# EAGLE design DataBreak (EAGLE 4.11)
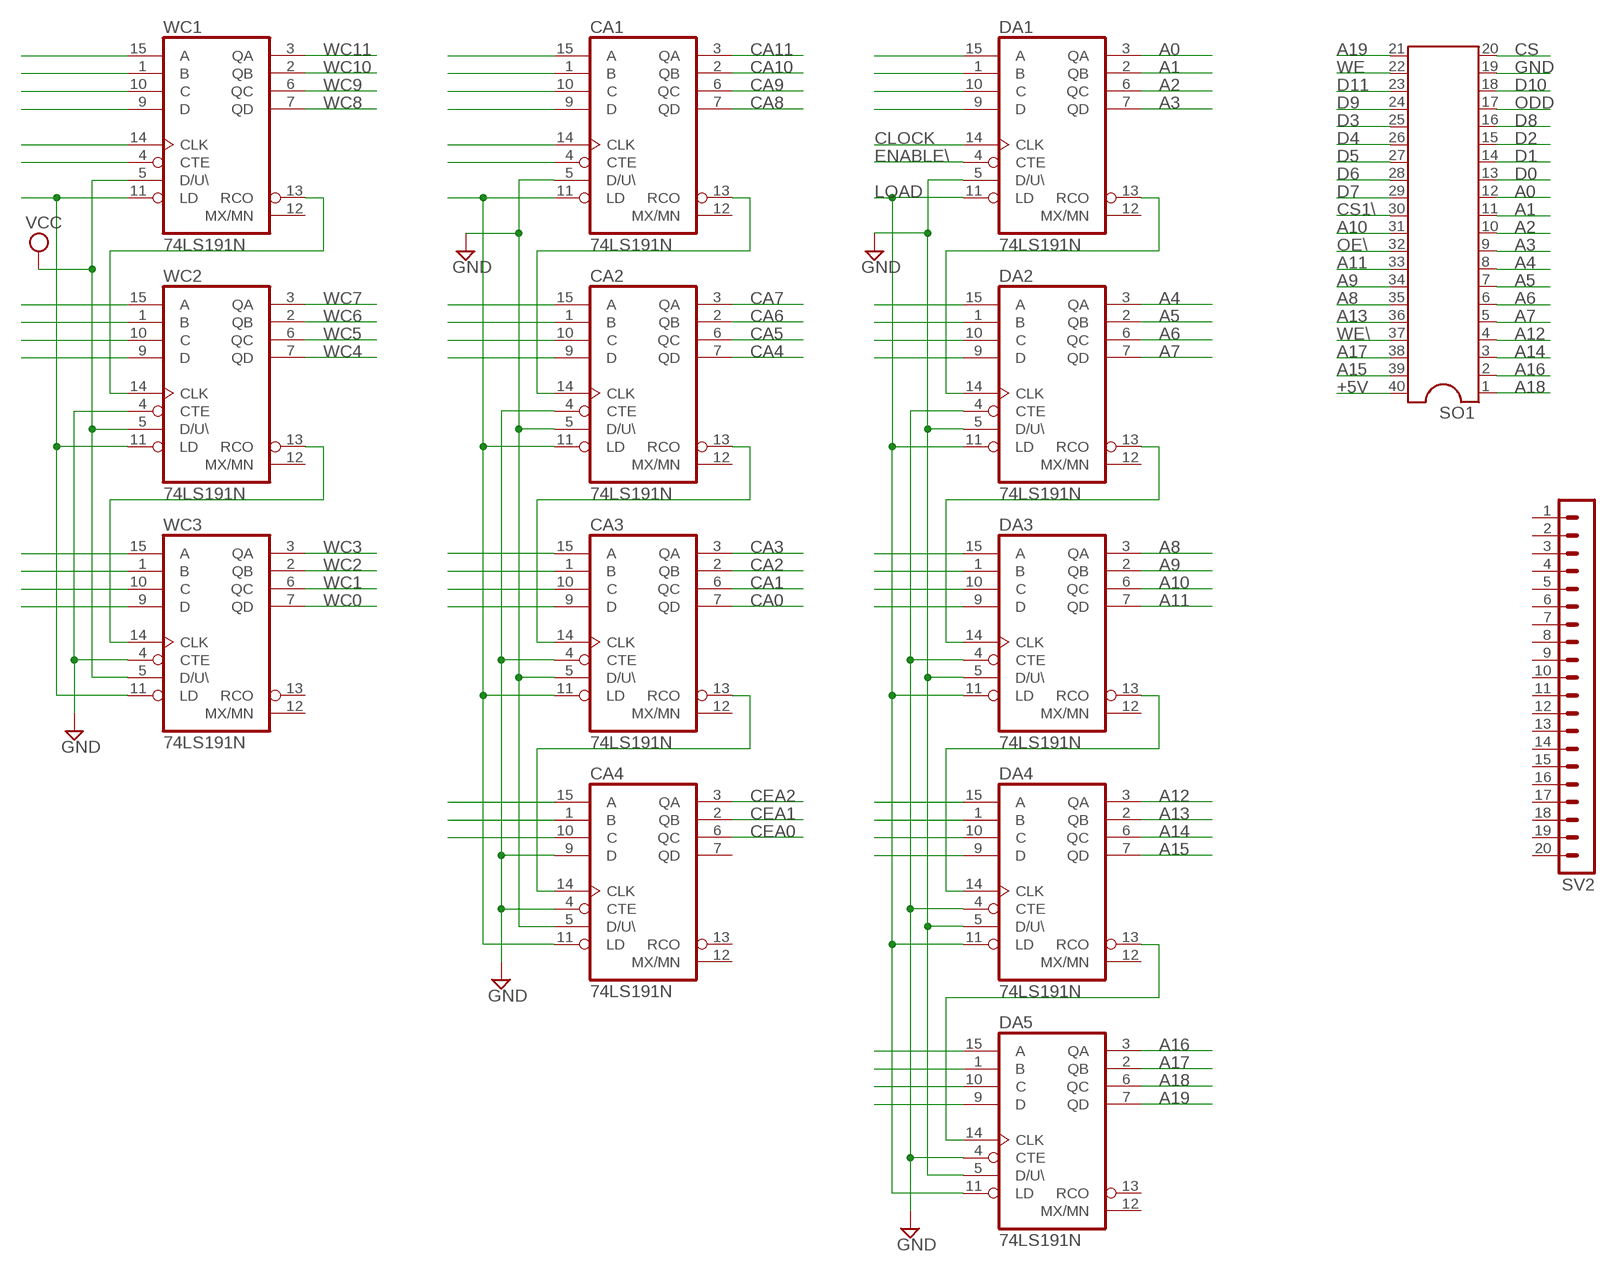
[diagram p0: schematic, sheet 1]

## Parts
CA1  74LS191N  74LS190N  [DIL16]
CA2  74LS191N  74LS190N  [DIL16]
CA3  74LS191N  74LS190N  [DIL16]
CA4  74LS191N  74LS190N  [DIL16]
DA1  74LS191N  74LS190N  [DIL16]
DA2  74LS191N  74LS190N  [DIL16]
DA3  74LS191N  74LS190N  [DIL16]
DA4  74LS191N  74LS190N  [DIL16]
DA5  74LS191N  74LS190N  [DIL16]
SO1  DIL40  [DIL40]
SV2  MA20-1L  [MA20-1L]
WC1  74LS191N  74LS190N  [DIL16]
WC2  74LS191N  74LS190N  [DIL16]
WC3  74LS191N  74LS190N  [DIL16]

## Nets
+5V: SO1.40
A0: DA1.3(QA) SO1.12
A1: DA1.2(QB) SO1.11
A2: DA1.6(QC) SO1.10
A3: DA1.7(QD) SO1.9
A4: DA2.3(QA) SO1.8
A5: DA2.2(QB) SO1.7
A6: DA2.6(QC) SO1.6
A7: DA2.7(QD) SO1.5
A8: DA3.3(QA) SO1.35
A9: DA3.2(QB) SO1.34
A10: DA3.6(QC) SO1.31
A11: DA3.7(QD) SO1.33
A12: DA4.3(QA) SO1.4
A13: DA4.2(QB) SO1.36
A14: DA4.6(QC) SO1.3
A15: DA4.7(QD) SO1.39
A16: DA5.3(QA) SO1.2
A17: DA5.2(QB) SO1.38
A18: DA5.6(QC) SO1.1
A19: DA5.7(QD) SO1.21
CA0: CA3.7(QD)
CA1: CA3.6(QC)
CA2: CA3.2(QB)
CA3: CA3.3(QA)
CA4: CA2.7(QD)
CA5: CA2.6(QC)
CA6: CA2.2(QB)
CA7: CA2.3(QA)
CA8: CA1.7(QD)
CA9: CA1.6(QC)
CA10: CA1.2(QB)
CA11: CA1.3(QA)
CEA0: CA4.6(QC)
CEA1: CA4.2(QB)
CEA2: CA4.3(QA)
CLOCK: DA1.14(CLK)
CS: SO1.20
CS1\: SO1.30
D0: SO1.13
D1: SO1.14
D2: SO1.15
D3: SO1.25
D4: SO1.26
D5: SO1.27
D6: SO1.28
D7: SO1.29
D8: SO1.16
D9: SO1.24
D10: SO1.18
D11: SO1.23
ENABLE\: DA1.4(CTE)
GND: CA1.5(D/U\) CA2.4(CTE) CA2.5(D/U\) CA3.4(CTE) CA3.5(D/U\) CA4.4(CTE) CA4.5(D/U\) CA4.9(D) DA1.5(D/U\) DA2.4(CTE) DA2.5(D/U\) DA3.4(CTE) DA3.5(D/U\) DA4.4(CTE) DA4.5(D/U\) DA5.4(CTE) DA5.5(D/U\) SO1.19 WC2.4(CTE) WC3.4(CTE)
LOAD: DA1.11(LD) DA2.11(LD) DA3.11(LD) DA4.11(LD) DA5.11(LD)
N$1: DA1.13(RCO) DA2.14(CLK)
N$2: DA1.15(A)
N$3: DA1.1(B)
N$4: DA1.10(C)
N$5: DA1.9(D)
N$6: DA2.15(A)
N$7: DA2.1(B)
N$8: DA2.10(C)
N$9: DA2.9(D)
N$10: DA2.13(RCO) DA3.14(CLK)
N$11: DA3.13(RCO) DA4.14(CLK)
N$12: DA4.13(RCO) DA5.14(CLK)
N$13: DA3.15(A)
N$14: DA3.1(B)
N$15: DA3.10(C)
N$16: DA3.9(D)
N$17: DA4.15(A)
N$18: CA1.15(A)
N$19: DA4.1(B)
N$20: DA4.9(D)
N$21: DA4.10(C)
N$22: DA5.15(A)
N$23: DA5.1(B)
N$24: DA5.10(C)
N$25: DA5.9(D)
N$26: WC1.13(RCO) WC2.14(CLK)
N$27: WC2.13(RCO) WC3.14(CLK)
N$28: CA1.13(RCO) CA2.14(CLK)
N$29: CA2.13(RCO) CA3.14(CLK)
N$30: CA3.13(RCO) CA4.14(CLK)
N$31: CA1.1(B)
N$32: CA1.14(CLK)
N$33: CA1.4(CTE)
N$34: CA1.10(C)
N$35: CA1.9(D)
N$36: CA2.1(B)
N$37: CA2.15(A)
N$38: CA2.9(D)
N$39: CA3.1(B)
N$40: CA3.10(C)
N$41: CA3.9(D)
N$42: CA4.15(A)
N$43: CA4.1(B)
N$44: CA4.10(C)
N$45: CA1.11(LD) CA2.11(LD) CA3.11(LD) CA4.11(LD)
N$46: WC1.11(LD) WC2.11(LD) WC3.11(LD)
N$47: WC1.15(A)
N$48: CA3.15(A)
N$49: CA2.10(C)
N$50: WC1.4(CTE)
N$51: WC1.14(CLK)
N$52: WC1.9(D)
N$53: WC1.1(B)
N$54: WC1.10(C)
N$55: WC2.15(A)
N$56: WC2.1(B)
N$57: WC2.10(C)
N$58: WC3.1(B)
N$59: WC3.15(A)
N$60: WC2.9(D)
N$61: WC3.10(C)
N$62: WC3.9(D)
ODD: SO1.17
OE\: SO1.32
VCC: WC1.5(D/U\) WC2.5(D/U\) WC3.5(D/U\)
WC0: WC3.7(QD)
WC1: WC3.6(QC)
WC2: WC3.2(QB)
WC3: WC3.3(QA)
WC4: WC2.7(QD)
WC5: WC2.6(QC)
WC6: WC2.2(QB)
WC7: WC2.3(QA)
WC8: WC1.7(QD)
WC9: WC1.6(QC)
WC10: WC1.2(QB)
WC11: WC1.3(QA)
WE: SO1.22
WE\: SO1.37
Unconnected: CA1.12(MX/MN) CA2.12(MX/MN) CA3.12(MX/MN) CA4.7(QD) CA4.12(MX/MN) CA4.13(RCO) DA1.12(MX/MN) DA2.12(MX/MN) DA3.12(MX/MN) DA4.12(MX/MN) DA5.12(MX/MN) DA5.13(RCO) SV2.1 SV2.2 SV2.3 SV2.4 SV2.5 SV2.6 SV2.7 SV2.8 SV2.9 SV2.10 SV2.11 SV2.12 SV2.13 SV2.14 SV2.15 SV2.16 SV2.17 SV2.18 SV2.19 SV2.20 WC1.12(MX/MN) WC2.12(MX/MN) WC3.12(MX/MN) WC3.13(RCO)

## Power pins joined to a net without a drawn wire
GND: CA1.8(GND) CA2.8(GND) CA3.8(GND) CA4.8(GND) DA1.8(GND) DA2.8(GND) DA3.8(GND) DA4.8(GND) DA5.8(GND) WC1.8(GND) WC2.8(GND) WC3.8(GND)
VCC: CA1.16(VCC) CA2.16(VCC) CA3.16(VCC) CA4.16(VCC) DA1.16(VCC) DA2.16(VCC) DA3.16(VCC) DA4.16(VCC) DA5.16(VCC) WC1.16(VCC) WC2.16(VCC) WC3.16(VCC)

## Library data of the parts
CA1-CA4 DA1-DA5 WC1-WC3 = 74xx-us:74*190: Synchronous UP/DOWN COUNTER
SO1 = ic-package:DIL40: Dual In Line
SV2 = con-lstb:MA20-1L: PIN HEADER

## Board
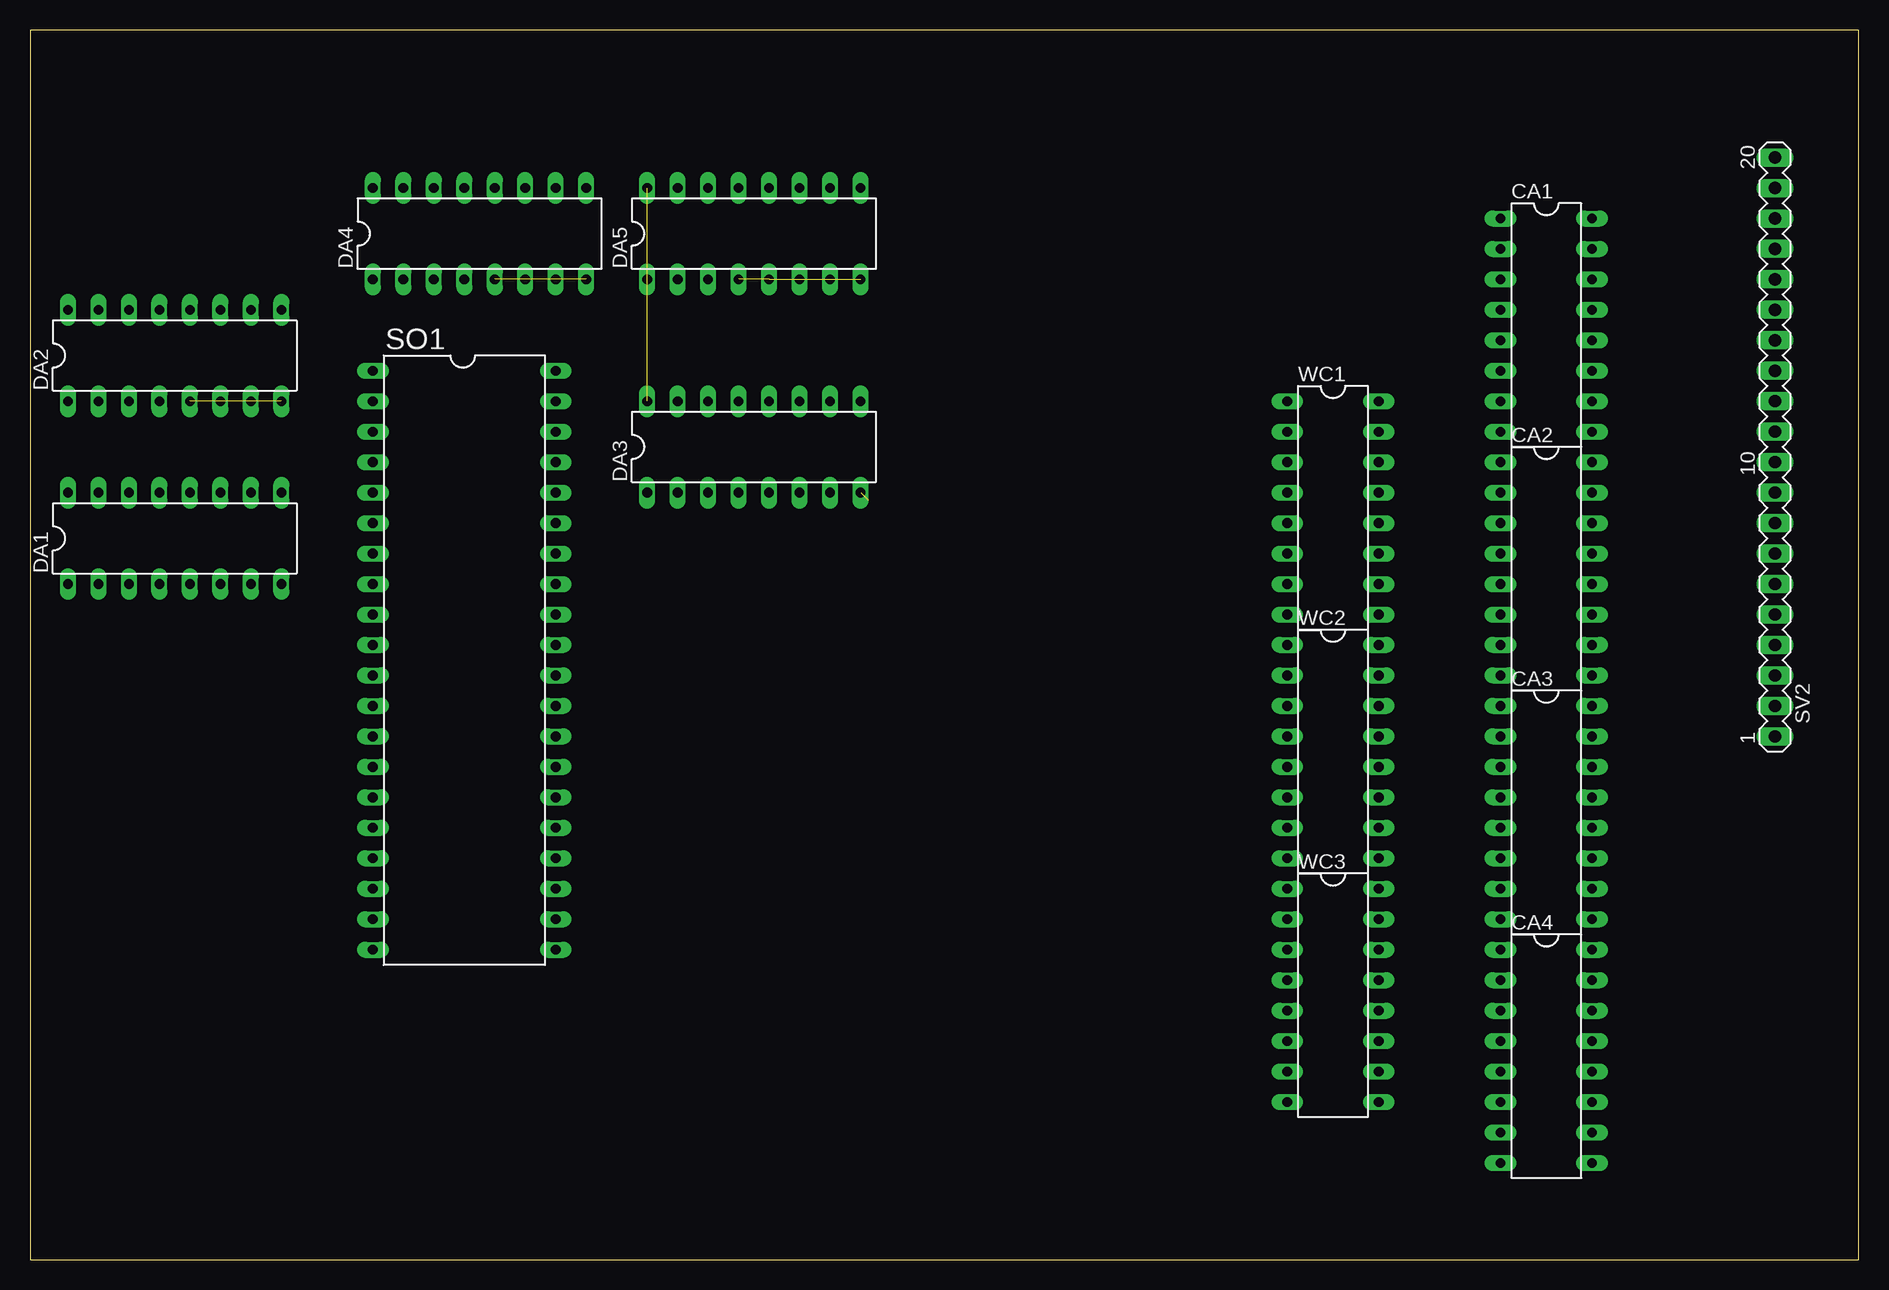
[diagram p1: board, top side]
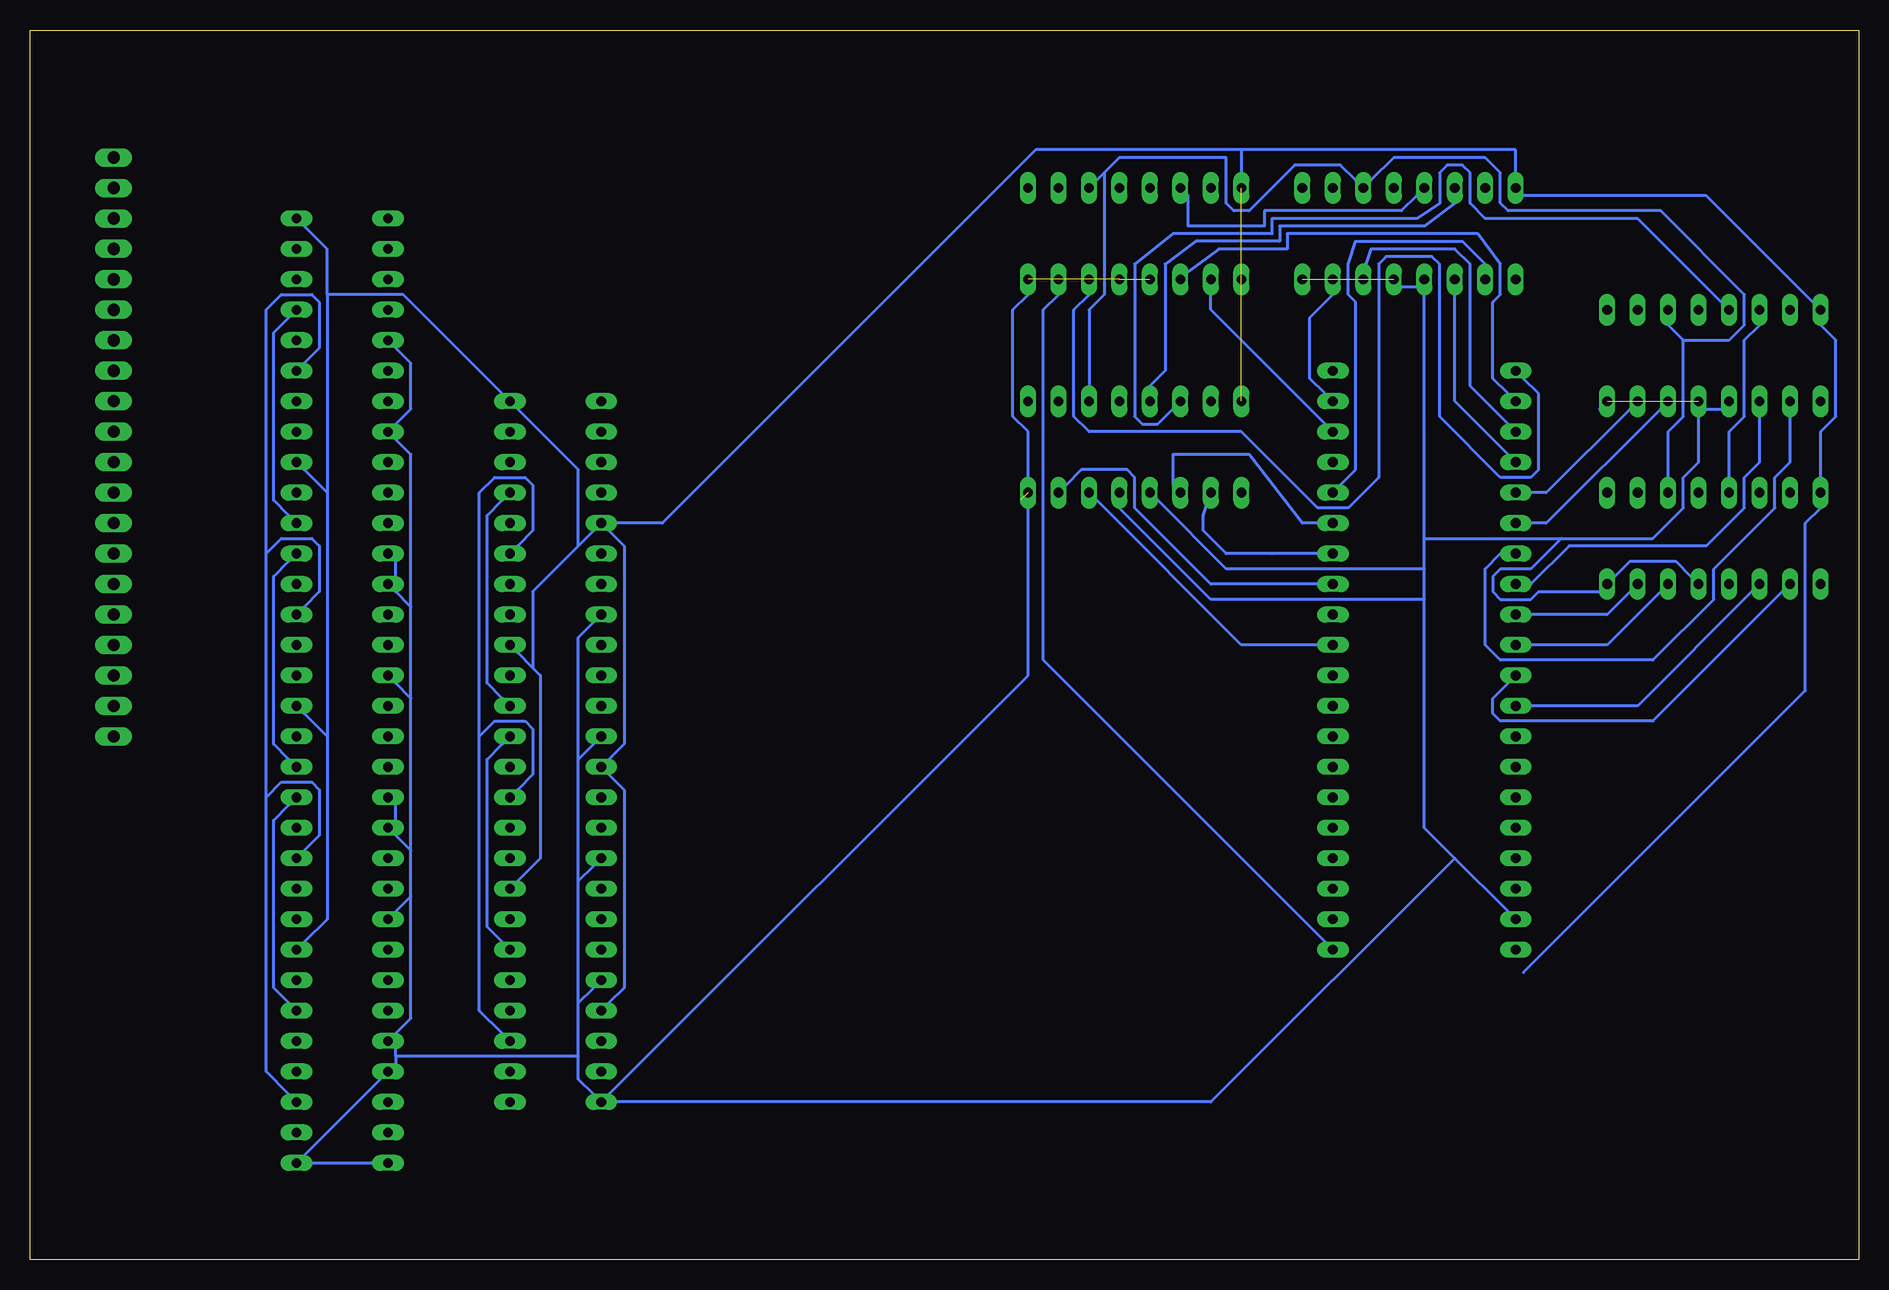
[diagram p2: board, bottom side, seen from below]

Size 152.38 x 102.54 mm. Coordinates in mm from the lower left corner, seen from the top.
Outline: 0,0 152.38,0 152.38,102.54 0,102.54 0,0
Copper layers (1*16): Top 0.035mm / dielectric 1.5mm / Bottom 0.035mm
Design rules "default": minimum track width 10mil, minimum drill 24mil, track to track 8mil, track to pad 8mil, pad to pad 8mil, via to via 8mil, smd to smd 8mil, copper to edge 40mil, drill to drill 8mil, minimum pad ring 10mil, minimum via ring 8mil, stop-mask expansion 4mil, vias tented up to drill 0mil, thermal gap 10mil

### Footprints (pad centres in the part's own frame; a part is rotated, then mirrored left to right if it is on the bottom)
DIL16 = drill 0.813 long: 1 -8.89,-3.81; 2 -6.35,-3.81; 3 -3.81,-3.81; 4 -1.27,-3.81; 5 1.27,-3.81; 6 3.81,-3.81; 7 6.35,-3.81; 8 8.89,-3.81; 9 8.89,3.81; 10 6.35,3.81; 11 3.81,3.81; 12 1.27,3.81; 13 -1.27,3.81; 14 -3.81,3.81; 15 -6.35,3.81; 16 -8.89,3.81
DIL40 = drill 0.813 long: 1 -24.13,-7.62; 2 -21.59,-7.62; 3 -19.05,-7.62; 4 -16.51,-7.62; 5 -13.97,-7.62; 6 -11.43,-7.62; 7 -8.89,-7.62; 8 -6.35,-7.62; 9 -3.81,-7.62; 10 -1.27,-7.62; 11 1.27,-7.62; 12 3.81,-7.62; 13 6.35,-7.62; 14 8.89,-7.62; 15 11.43,-7.62; 16 13.97,-7.62; 17 16.51,-7.62; 18 19.05,-7.62; 19 21.59,-7.62; 20 24.13,-7.62; 21 24.13,7.62; 22 21.59,7.62; 23 19.05,7.62; 24 16.51,7.62; 25 13.97,7.62; 26 11.43,7.62; 27 8.89,7.62; 28 6.35,7.62; 29 3.81,7.62; 30 1.27,7.62; 31 -1.27,7.62; 32 -3.81,7.62; 33 -6.35,7.62; 34 -8.89,7.62; 35 -11.43,7.62; 36 -13.97,7.62; 37 -16.51,7.62; 38 -19.05,7.62; 39 -21.59,7.62; 40 -24.13,7.62
MA20-1L = drill 1.016 long: 1 24.13,0; 2 21.59,0; 3 19.05,0; 4 16.51,0; 5 13.97,0; 6 11.43,0; 7 8.89,0; 8 6.35,0; 9 3.81,0; 10 1.27,0; 11 -1.27,0; 12 -3.81,0; 13 -6.35,0; 14 -8.89,0; 15 -11.43,0; 16 -13.97,0; 17 -16.51,0; 18 -19.05,0; 19 -21.59,0; 20 -24.13,0

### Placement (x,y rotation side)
CA1  126.36,77.94 270 top
CA2  126.36,57.62 270 top
CA3  126.36,37.3 270 top
CA4  126.36,16.98 270 top
DA1  12.06,60.16 0 top
DA2  12.06,75.4 0 top
DA3  60.32,67.78 0 top
DA4  37.46,85.56 0 top
DA5  60.32,85.56 0 top
SO1  36.19,50 270 top
SV2  145.41,67.78 270 top
WC1  108.58,62.7 270 top
WC2  108.58,42.38 270 top
WC3  108.58,22.06 270 top

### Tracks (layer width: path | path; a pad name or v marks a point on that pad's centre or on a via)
A0
  Bottom 0.254: DA1.3 8.89,55.71 18.41,46.19 27.3,46.19 SO1.12
A1
  Bottom 0.254: DA1.2 6.34,55.71 17.14,44.92 29.84,44.92 30.47,45.55 30.47,46.82 29.2,48.09 SO1.11
A2
  Bottom 0.254: DA1.6 16.5,55.71 20.95,51.27 27.3,51.27 SO1.10
A3
  Bottom 0.254: DA1.7 19.04,55.71 20.95,53.81 27.3,53.81 SO1.9
A4
  Bottom 0.254: DA2.3 8.25,70.32 8.25,66.51 9.52,65.24 9.52,62.7 12.7,59.52 24.12,59.52 27.3,56.35 SO1.8
A5
  Bottom 0.254: DA2.2 5.71,70.32 5.71,66.51 6.98,65.24 6.98,62.7 12.06,57.62 12.06,55.08 17.14,50 29.84,50 31.11,51.27 31.11,57.62 29.84,58.89 SO1.7
A6
  Bottom 0.254: DA2.6 16.5,70.95 26.03,61.43 27.3,61.43 SO1.6
A7
  Bottom 0.254: DA2.7 19.04,70.95 26.03,63.97 27.3,63.97 SO1.5
A8
  Bottom 0.254: SO1.35 45.08,61.43 46.35,61.43 50.8,67.14 57.15,67.14 57.15,64.61 DA3.3
A9
  Bottom 0.254: SO1.34 45.08,58.89 48.89,58.89 52.7,58.89 54.61,60.8 54.61,62.06 DA3.2
A10
  Bottom 0.254: SO1.31 45.08,51.27 51.43,51.27 63.5,63.34 DA3.6
A11
  Bottom 0.254: SO1.33 45.08,56.35 53.97,56.35 60.32,62.7 60.32,65.24 60.96,65.88 64.77,65.88 66.03,64.61 DA3.7
A12
  Bottom 0.254: SO1.4 29.2,67.14 33.65,71.59 33.65,80.48 DA4.3
A13
  Bottom 0.254: SO1.36 43.18,64.61 41.91,65.88 41.91,79.84 42.54,80.48 42.54,83.02 41.91,84.92 33.02,84.92 31.11,83.02 DA4.2
A14
  Bottom 0.254: SO1.3 29.2,69.69 32.38,72.86 32.38,83.02 33.65,84.29 40.64,84.29 41.27,82.39 DA4.6
A15
  Bottom 0.254: SO1.39 44.45,72.22 45.72,73.5 45.72,78.58 43.81,80.48 DA4.7
A16
  Bottom 0.254: SO1.2 29.2,72.22 30.47,73.5 30.47,79.84 29.84,80.48 29.84,83.02 31.74,85.56 47.62,85.56 47.62,84.29 53.34,84.29 55.88,82.39 DA5.3
A17
  Bottom 0.254: SO1.38 44.45,69.69 53.97,79.21 53.97,80.48 DA5.2
A18
  Bottom 0.254: SO1.1 27.93,73.5 26.66,72.22 26.66,65.88 27.3,65.24 29.84,65.24 34.92,70.32 34.92,83.02 35.55,83.66 39.37,83.66 40,83.02 40,65.24 42.54,62.7 45.08,62.7 51.43,69.05 64.13,69.05 65.4,70.32 65.4,79.21 64.13,80.48 DA5.6
A19
  Bottom 0.254: SO1.21 44.45,26.5 67.94,50 67.94,79.21 66.67,80.48 DA5.7
GND  (5 unrouted)
  Bottom 0.254: DA2.4 11.43,70.95 12.7,70.95 DA2.5 13.33,70.32 13.33,66.51 14.6,65.24 14.6,62.7 17.14,60.16 24.76,60.16 | DA5.8 69.21,80.48 70.48,79.21 70.48,70.32 69.21,69.05 69.21,65.24 DA3.8 69.21,62.7 69.21,48.73 104.13,13.81 WC3.8 | DA4.5 38.1,81.11 36.83,81.11 DA4.4 36.19,80.48 36.19,60.16 | DA1.5 13.97,56.98 15.24,58.25 19.04,58.25 20.31,56.98 DA1.8 21.58,55.71 26.66,55.71 27.3,55.08 29.84,55.08 30.47,55.71 30.47,56.98 29.84,57.62 27.3,57.62 24.76,60.16 | 21.58,70.95 DA2.8 | 106.67,16.98 106.67,21.42 | 106.67,16.98 106.67,15.08 105.41,13.81 WC3.8 | 106.67,21.42 105.41,22.7 WC3.4 | 106.67,31.58 105.41,32.85 WC2.8 | 106.67,21.42 106.67,31.58 | 106.67,41.74 105.41,43.02 WC2.4 | 106.67,31.58 106.67,41.74 | 106.67,41.74 106.67,51.91 105.41,53.17 WC1.8 | 121.91,16.98 121.91,17.61 CA4.4 121.91,18.88 120.64,20.15 120.64,30.31 | 121.91,16.98 121.91,16.34 CA4.5 123.19,15.08 129.53,8.73 CA4.9 128.9,8.09 123.82,8.09 CA4.8 | CA1.5 121.91,76.03 120.64,74.77 120.64,70.95 121.91,69.69 CA1.8 121.91,68.41 120.64,67.14 120.64,54.45 | CA2.4 121.91,58.25 121.91,56.98 CA2.5 121.91,55.71 120.64,54.45 | 120.64,30.31 121.91,29.04 CA3.8 | 120.64,30.31 120.64,34.12 | 120.64,34.12 121.91,35.39 CA3.5 121.91,36.66 121.91,37.94 CA3.4 | 120.64,46.82 121.91,48.09 CA2.8 | 120.64,34.12 120.64,46.82 | 120.64,46.82 120.64,54.45 | 106.67,16.98 121.91,16.98 | 33.65,33.49 36.19,36.03 36.19,55.08 | 33.65,33.49 29.2,29.04 SO1.19 | 36.19,57.62 36.19,60.16 | 36.19,55.08 36.19,57.62 | 36.19,57.62 52.7,57.62 58.41,63.34 DA3.4 | 36.19,55.08 53.97,55.08 61.59,62.7 DA3.5 | 36.19,60.16 24.76,60.16 | 33.65,33.49 53.97,13.17 103.5,13.17 WC3.8
LOAD
  Bottom 0.254: 14.6,76.67 14.6,70.32 15.87,69.05 15.87,65.24 DA1.11 | 14.6,76.67 15.87,77.94 DA2.11 | 62.86,90.64 63.5,90 DA5.11 | 62.86,90.64 62.23,91.28 61.59,91.91 52.7,91.91 52.7,88.1 52.07,87.47 50.8,87.47 46.98,91.28 43.18,91.28 41.91,90 DA4.11 40.64,90 38.73,91.91 31.11,91.91 29.84,90.64 29.84,88.1 29.2,87.47 16.5,87.47 9.52,80.48 9.52,77.94 10.79,76.67 14.6,76.67 | 62.86,90.64 62.86,80.48 64.13,79.21 64.13,72.86 DA3.11
N$1
  Bottom 0.254: DA1.13 10.79,65.24 10.79,69.05 9.52,70.32 9.52,76.67 8.25,77.94 DA2.14
N$10
  Bottom 0.254: 11.43,79.84 DA2.13 11.43,79.84 | DA3.14 57.15,70.95 58.41,69.69 59.69,69.69 60.32,70.32 60.32,83.02 57.15,85.56 48.89,85.56 48.89,86.83 36.83,86.83 34.92,88.1 34.92,90.64 34.29,91.28 33.02,91.28 32.38,90.64 32.38,88.1 31.11,86.83 18.41,86.83 11.43,79.84
N$11
  Bottom 0.254: DA4.14 33.65,88.1 36.19,86.19 48.26,86.19 48.26,84.92 55.24,84.92 57.78,83.02 57.78,74.13 59.05,72.86 DA3.13
N$12
  Bottom 0.254: DA4.13 36.83,88.73 38.1,87.47 49.53,87.47 49.53,86.19 55.88,86.19 55.88,88.73 DA5.14
N$26
  Bottom 0.254: WC2.14 113.02,46.82 114.3,48.09 114.3,62.06 113.02,63.34 WC1.13
N$27
  Bottom 0.254: WC3.14 113.02,26.5 114.3,27.77 114.3,41.74 113.02,43.02 WC2.13
N$28
  Bottom 0.254: CA2.14 130.81,62.06 132.07,63.34 132.07,77.3 130.81,78.58 CA1.13
N$29
  Bottom 0.254: CA3.14 130.81,41.74 132.07,43.02 132.07,56.98 130.81,58.25 CA2.13
N$30
  Bottom 0.254: CA4.14 130.81,21.42 132.07,22.7 132.07,36.66 130.81,37.94 CA3.13
N$45
  Bottom 0.254: 132.71,38.57 132.71,15.71 130.81,13.81 CA4.11 | 132.71,38.57 131.44,39.84 128.9,39.84 128.27,39.2 128.27,35.39 129.53,34.12 CA3.11 | 132.71,58.89 131.44,60.16 128.9,60.16 128.27,59.52 128.27,55.71 129.53,54.45 CA2.11 | 132.71,38.57 132.71,58.89 | 132.71,58.89 132.71,79.21 131.44,80.48 128.9,80.48 128.27,79.84 128.27,76.03 129.53,74.77 CA1.11
N$46
  Bottom 0.254: 114.93,43.65 114.93,20.79 113.02,18.88 WC3.11 | 114.93,43.65 113.66,44.92 111.12,44.92 110.48,44.28 110.48,40.48 111.75,39.2 WC2.11 | 114.93,43.65 114.93,63.97 113.66,65.24 111.12,65.24 110.48,64.61 110.48,60.8 111.75,59.52 WC1.11
VCC  (1 unrouted)
  Bottom 0.254: DA2.16 3.17,77.94 1.9,76.67 1.9,70.32 3.17,69.05 3.17,65.24 DA1.16 3.17,62.7 4.44,61.43 4.44,47.46 27.93,23.96 | 51.43,92.55 28.57,92.55 28.57,90.64 DA4.16 27.93,88.73 12.7,88.73 3.8,79.84 | 51.43,92.55 68.57,92.55 99.69,61.43 103.5,61.43 WC1.5 | DA2.16 3.8,79.84 | 51.43,92.55 51.43,90.64 DA5.16 | DA2.16 3.8,79.84 | WC3.5 104.13,21.42 102.86,22.7 102.86,39.2 104.13,40.48 WC2.5 104.13,41.74 102.86,43.02 102.86,59.52 104.13,60.8 WC1.5 | 110.48,49.37 111.75,50.63 WC2.16 | 110.48,49.37 109.85,48.73 109.85,33.49 111.75,31.58 WC3.16 | 106.67,59.52 110.48,55.71 110.48,49.37 | 106.67,59.52 105.41,60.8 WC1.5 | 106.67,59.52 106.67,65.88 111.75,70.95 WC1.16 113.02,72.22 121.28,80.48 127.63,80.48 | 127.63,43.65 127.63,28.41 129.53,26.5 CA4.16 | 127.63,43.65 129.53,45.55 CA3.16 | 127.63,63.97 129.53,65.88 CA2.16 | 127.63,63.97 127.63,43.65 | 127.63,80.48 127.63,63.97 | 127.63,80.48 127.63,84.29 129.53,86.19 CA1.16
